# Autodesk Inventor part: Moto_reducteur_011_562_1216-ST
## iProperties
Created: 2010-04
Part Number: Moto_reducteur_011_562_1216-ST
Document SubType Name: Modeling
Designer: Alex_Cyril
Norme de conversion: STEP AP203
Nom du fichier: 011-562-1216.STEP
Préprocesseur: SolidWorks 2009
Postprocesseur: Build: 391, Release: 11 SP3 - Date: Tue 06/05/2007
Unités envoyées: MILLIMETERS
Incertitude: 1e-05
Author: Alex_Cyril
